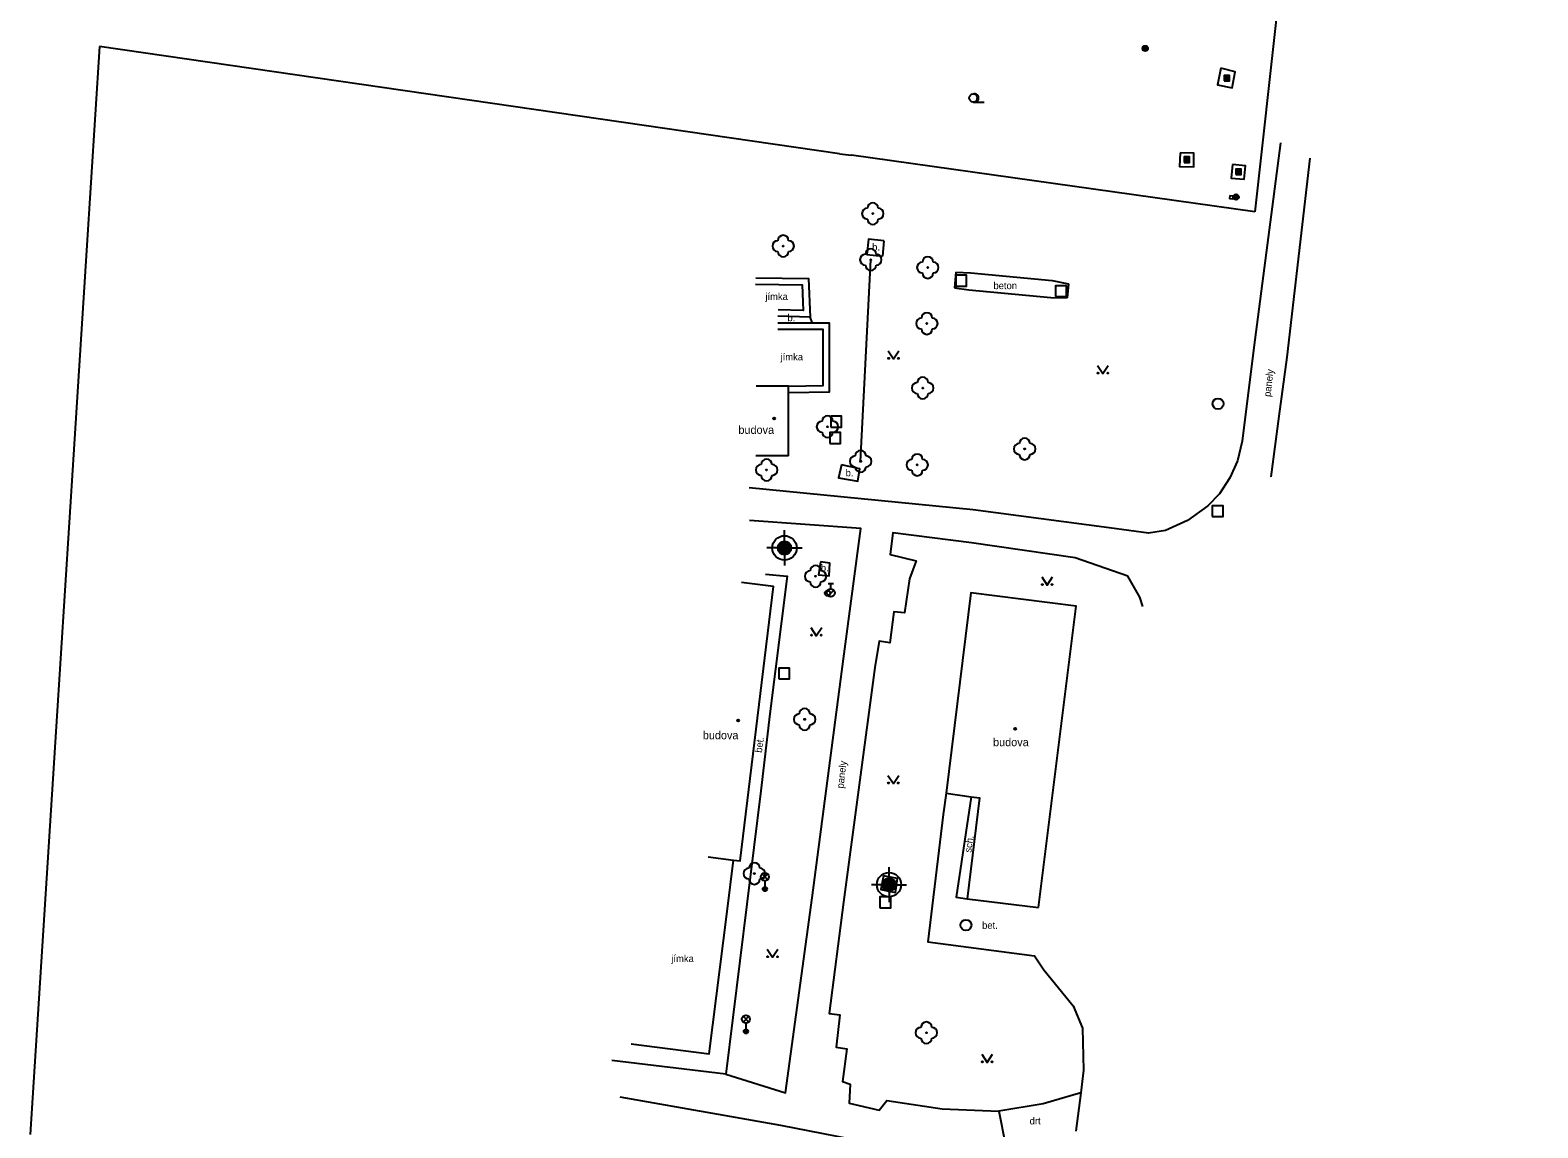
# Model space of a CAD drawing. Extents: x -540235 to -537963, y -1184915 to -1183660.
# Drawn here: x -540179 to -540039.8, y -1183965.3 to -1183863.9 of the extents above; entities that cross this region are included whole.
import ezdxf

# ---------------------------------------------------------------- set-up
doc = ezdxf.new("R2010")
doc.units = 0
for name, color, linetype in [('Vrstva 10', 7, 'Continuous'), ('Vrstva 11', 7, 'Continuous'), ('Vrstva 21', 7, 'Continuous'), ('Vrstva 22', 7, 'Continuous'), ('Vrstva 24', 7, 'Continuous'), ('Vrstva 25', 7, 'Continuous'), ('Vrstva 26', 7, 'Continuous'), ('Vrstva 27', 7, 'Continuous'), ('Vrstva 28', 7, 'Continuous'), ('Vrstva 33', 7, 'Continuous'), ('Vrstva 35', 7, 'Continuous'), ('Vrstva 36', 7, 'Continuous'), ('Vrstva 39', 7, 'Continuous'), ('Vrstva 40', 7, 'Continuous'), ('Vrstva 41', 7, 'Continuous'), ('Vrstva 5', 7, 'Continuous'), ('Vrstva 7', 7, 'Continuous'), ('Vrstva 8', 7, 'Continuous')]:
    doc.layers.add(name, color=color, linetype=linetype)

msp = doc.modelspace()

# ---------------------------------------------------------------- linework, layer by layer
at = {"layer": 'Vrstva 10'}
for points in [[(-540094.47, -1183934.39), (-540094.73, -1183936.35), (-540096.14, -1183948.09), (-540086.31, -1183949.41), (-540085.44, -1183950.68), (-540082.72, -1183954.01), (-540081.86, -1183956.08), (-540081.78, -1183959.97), (-540082.04, -1183962.04)], [(-540082.04, -1183962.04), (-540082.48, -1183965.59)]]:
    msp.add_lwpolyline(points, dxfattribs=at)
at = {"layer": 'Vrstva 11'}
msp.add_line((-540100.2, -1183883.36), (-540100.34, -1183884.79), dxfattribs=at)
for points in [[(-540063.59, -1183874.34), (-540066.05, -1183893.22), (-540067.13, -1183901.88), (-540067.57, -1183903.7), (-540068.27, -1183905.25), (-540069.24, -1183906.74), (-540070.3, -1183907.86), (-540072.17, -1183909.19), (-540074.22, -1183910.11), (-540075.78, -1183910.38), (-540079.41, -1183909.87), (-540091.96, -1183908.22), (-540112.64, -1183906.17)], [(-540060.89, -1183875.73), (-540063, -1183894.11), (-540063.75, -1183899.57), (-540064.48, -1183905.17)], [(-540100.2, -1183883.36), (-540101.6331, -1183883.2197), (-540101.7731, -1183884.6497), (-540100.34, -1183884.79)], [(-540106.79, -1183890.97), (-540107.02, -1183890.42)], [(-540104.13, -1183904.05), (-540104.4, -1183905.27), (-540102.6, -1183905.57), (-540102.41, -1183904.42), (-540104.13, -1183904.05)], [(-540114.79, -1183960.33), (-540109.3, -1183962.06), (-540106.84, -1183944.05), (-540103.94, -1183921.98), (-540102.32, -1183909.95), (-540112.6, -1183909.21)], [(-540076.31, -1183917.14), (-540076.57, -1183916.27), (-540077.68, -1183914.35), (-540082.56, -1183912.64), (-540092.13, -1183911.25), (-540099.38, -1183910.33), (-540099.63, -1183912.33), (-540097.24, -1183912.93), (-540097.85, -1183914.59), (-540098.3, -1183917.71), (-540099.28, -1183917.62), (-540099.67, -1183920.5), (-540100.63, -1183920.34), (-540101.04, -1183922.76), (-540103.92, -1183944.43), (-540105.27, -1183954.72), (-540104.28, -1183954.85), (-540104.6, -1183957.82), (-540103.64, -1183957.98), (-540104.02, -1183961.01), (-540103.31, -1183961.24), (-540103.4, -1183963), (-540100.63, -1183963.66), (-540099.93, -1183962.77), (-540094.82, -1183963.54), (-540089.6, -1183963.73)], [(-540106.07, -1183913.02), (-540106.23, -1183914.23), (-540105.25, -1183914.31), (-540105.19, -1183913.14), (-540106.07, -1183913.02)], [(-540092.16, -1183934.71), (-540093.53, -1183943.98), (-540092.51, -1183944.12)], [(-540100.23, -1183942), (-540100.49, -1183943.27), (-540099.12, -1183943.56), (-540098.94, -1183942.25), (-540100.23, -1183942)], [(-540082.04, -1183962.04), (-540085.49, -1183963.05), (-540089.6, -1183963.73)], [(-540089.02, -1183966.69), (-540095.17, -1183966.92), (-540097.23, -1183967.24), (-540097.81, -1183968.1), (-540087.88, -1183969.31), (-540088.51, -1183975.15), (-540101.65, -1183974.03), (-540100.59, -1183966.86), (-540109.71, -1183965.07), (-540124.55, -1183962.46)], [(-540089.6, -1183963.73), (-540089.02, -1183966.69)]]:
    msp.add_lwpolyline(points, dxfattribs=at)
at = {"layer": 'Vrstva 21'}
msp.add_lwpolyline([(-540102.35, -1183903.74), (-540101.41, -1183885.12)], dxfattribs=at)
at = {"layer": 'Vrstva 22'}
for centre in [(-540101.23, -1183880.86), (-540109.5, -1183883.86), (-540101.41, -1183885.12), (-540096.15, -1183885.84), (-540096.24, -1183891.01), (-540096.62, -1183896.97), (-540105.41, -1183900.54), (-540102.35, -1183903.74), (-540087.21, -1183902.59), (-540111.03, -1183904.53), (-540097.13, -1183904.06), (-540106.51, -1183914.35), (-540107.52, -1183927.56), (-540112.16, -1183941.8), (-540096.28, -1183956.5)]:
    msp.add_circle(centre, 0.05, dxfattribs=at)
for centre, start, end in [((-540101.23, -1183880.36), 0, 180), ((-540101.73, -1183880.86), 90, 270), ((-540101.23, -1183881.36), 180, 0), ((-540100.73, -1183880.86), 270, 90), ((-540109.5, -1183883.36), 0, 180), ((-540110, -1183883.86), 90, 270), ((-540109.5, -1183884.36), 180, 0), ((-540109, -1183883.86), 270, 90), ((-540101.41, -1183884.62), 0, 180), ((-540101.91, -1183885.12), 90, 270), ((-540101.41, -1183885.62), 180, 0), ((-540100.91, -1183885.12), 270, 90), ((-540096.65, -1183885.84), 90, 270), ((-540096.15, -1183885.34), 0, 180), ((-540095.65, -1183885.84), 270, 90), ((-540096.15, -1183886.34), 180, 0), ((-540096.74, -1183891.01), 90, 270), ((-540096.24, -1183890.51), 0, 180), ((-540095.74, -1183891.01), 270, 90), ((-540096.24, -1183891.51), 180, 0), ((-540097.12, -1183896.97), 90, 270), ((-540096.62, -1183896.47), 0, 180), ((-540096.12, -1183896.97), 270, 90), ((-540096.62, -1183897.47), 180, 0), ((-540105.41, -1183900.04), 0, 180), ((-540105.91, -1183900.54), 90, 270), ((-540105.41, -1183901.04), 180, 0), ((-540104.91, -1183900.54), 270, 90), ((-540087.71, -1183902.59), 90, 270), ((-540087.21, -1183902.09), 0, 180), ((-540086.71, -1183902.59), 270, 90), ((-540111.03, -1183904.03), 0, 180), ((-540102.85, -1183903.74), 90, 270), ((-540102.35, -1183903.24), 0, 180), ((-540101.85, -1183903.74), 270, 90), ((-540097.63, -1183904.06), 90, 270), ((-540097.13, -1183903.56), 0, 180), ((-540096.63, -1183904.06), 270, 90), ((-540087.21, -1183903.09), 180, 0), ((-540111.53, -1183904.53), 90, 270), ((-540111.03, -1183905.03), 180, 0), ((-540110.53, -1183904.53), 270, 90), ((-540102.35, -1183904.24), 180, 0), ((-540097.13, -1183904.56), 180, 0), ((-540106.51, -1183913.85), 0, 180), ((-540107.01, -1183914.35), 90, 270), ((-540106.51, -1183914.85), 180, 0), ((-540106.01, -1183914.35), 270, 90), ((-540108.02, -1183927.56), 90, 270), ((-540107.52, -1183927.06), 0, 180), ((-540107.02, -1183927.56), 270, 90), ((-540107.52, -1183928.06), 180, 0), ((-540112.66, -1183941.8), 90, 270), ((-540112.16, -1183941.3), 0, 180), ((-540111.66, -1183941.8), 270, 90), ((-540112.16, -1183942.3), 180, 0), ((-540096.78, -1183956.5), 90, 270), ((-540096.28, -1183956), 0, 180), ((-540095.78, -1183956.5), 270, 90), ((-540096.28, -1183957), 180, 0)]:
    msp.add_arc(centre, 0.5, start, end, dxfattribs=at)
at = {"layer": 'Vrstva 24'}
for points in [[(-540068.28, -1183879.2), (-540068.3, -1183879.5)], [(-540068.28, -1183879.2), (-540067.9807, -1183879.22), (-540068.0007, -1183879.52), (-540068.3, -1183879.5)]]:
    msp.add_lwpolyline(points, dxfattribs=at)
at = {"layer": 'Vrstva 25'}
for points in [[(-540068.81, -1183868.61), (-540068.31, -1183868.61), (-540068.31, -1183868.11), (-540068.81, -1183868.11)], [(-540068.76, -1183868.56), (-540068.36, -1183868.56), (-540068.36, -1183868.16), (-540068.76, -1183868.16)], [(-540068.71, -1183868.51), (-540068.41, -1183868.51), (-540068.41, -1183868.21), (-540068.71, -1183868.21)], [(-540068.66, -1183868.46), (-540068.46, -1183868.46), (-540068.46, -1183868.26), (-540068.66, -1183868.26)], [(-540068.61, -1183868.41), (-540068.51, -1183868.41), (-540068.51, -1183868.31), (-540068.61, -1183868.31)], [(-540072.4871, -1183876.1277), (-540071.9871, -1183876.1277), (-540071.9871, -1183875.6277), (-540072.4871, -1183875.6277)], [(-540072.4371, -1183876.0777), (-540072.0371, -1183876.0777), (-540072.0371, -1183875.6777), (-540072.4371, -1183875.6777)], [(-540072.3871, -1183876.0277), (-540072.0871, -1183876.0277), (-540072.0871, -1183875.7277), (-540072.3871, -1183875.7277)], [(-540072.3371, -1183875.9777), (-540072.1371, -1183875.9777), (-540072.1371, -1183875.7777), (-540072.3371, -1183875.7777)], [(-540072.2871, -1183875.9277), (-540072.1871, -1183875.9277), (-540072.1871, -1183875.8277), (-540072.2871, -1183875.8277)], [(-540067.73, -1183877.26), (-540067.23, -1183877.26), (-540067.23, -1183876.76), (-540067.73, -1183876.76)], [(-540067.68, -1183877.21), (-540067.28, -1183877.21), (-540067.28, -1183876.81), (-540067.68, -1183876.81)], [(-540067.63, -1183877.16), (-540067.33, -1183877.16), (-540067.33, -1183876.86), (-540067.63, -1183876.86)], [(-540067.58, -1183877.11), (-540067.38, -1183877.11), (-540067.38, -1183876.91), (-540067.58, -1183876.91)], [(-540067.53, -1183877.06), (-540067.43, -1183877.06), (-540067.43, -1183876.96), (-540067.53, -1183876.96)]]:
    msp.add_lwpolyline(points, close=True, dxfattribs=at)
for centre, radius in [((-540076.08, -1183865.61), 0.25), ((-540076.08, -1183865.61), 0.2), ((-540076.08, -1183865.61), 0.15), ((-540076.08, -1183865.61), 0.1), ((-540076.08, -1183865.61), 0.05), ((-540067.7, -1183879.33), 0.25), ((-540067.7, -1183879.33), 0.2), ((-540067.7, -1183879.33), 0.15), ((-540067.7, -1183879.33), 0.1), ((-540067.7, -1183879.33), 0.05)]:
    msp.add_circle(centre, radius, dxfattribs=at)
at = {"layer": 'Vrstva 26'}
for points in [[(-540093.57, -1183887.55), (-540092.57, -1183887.55), (-540092.57, -1183886.55), (-540093.57, -1183886.55)], [(-540084.35, -1183888.52), (-540083.35, -1183888.52), (-540083.35, -1183887.52), (-540084.35, -1183887.52)], [(-540105.11, -1183900.58), (-540104.11, -1183900.58), (-540104.11, -1183899.58), (-540105.11, -1183899.58)], [(-540105.2, -1183902.08), (-540104.2, -1183902.08), (-540104.2, -1183901.08), (-540105.2, -1183901.08)], [(-540069.9, -1183908.84), (-540068.9, -1183908.84), (-540068.9, -1183907.84), (-540069.9, -1183907.84)], [(-540109.91, -1183923.82), (-540108.91, -1183923.82), (-540108.91, -1183922.82), (-540109.91, -1183922.82)], [(-540100.57, -1183944.96), (-540099.57, -1183944.96), (-540099.57, -1183943.96), (-540100.57, -1183943.96)]]:
    msp.add_lwpolyline(points, close=True, dxfattribs=at)
at = {"layer": 'Vrstva 27'}
for centre in [(-540069.36, -1183898.42), (-540092.63, -1183946.56)]:
    msp.add_circle(centre, 0.5, dxfattribs=at)
at = {"layer": 'Vrstva 28'}
for p, q in [((-540105.36, -1183915.005), (-540104.86, -1183915.005)), ((-540105.11, -1183915.505), (-540105.11, -1183915.005)), ((-540105.368, -1183916.152), (-540104.838, -1183915.622))]:
    msp.add_line(p, q, dxfattribs=at)
for centre, radius in [((-540105.4, -1183915.91), 0.25), ((-540105.11, -1183915.88), 0.375)]:
    msp.add_circle(centre, radius, dxfattribs=at)
at = {"layer": 'Vrstva 33'}
for p, q in [((-540111.455, -1183942.37), (-540110.925, -1183941.84)), ((-540111.455, -1183941.84), (-540110.925, -1183942.37)), ((-540111.19, -1183942.48), (-540111.19, -1183943.23)), ((-540113.205, -1183955.51), (-540112.675, -1183954.98)), ((-540113.205, -1183954.98), (-540112.675, -1183955.51)), ((-540112.94, -1183955.62), (-540112.94, -1183956.37))]:
    msp.add_line(p, q, dxfattribs=at)
for centre, radius in [((-540111.19, -1183942.105), 0.375), ((-540111.19, -1183943.23), 0.2), ((-540111.19, -1183943.23), 0.1445), ((-540111.19, -1183943.23), 0.0876), ((-540112.94, -1183955.245), 0.375), ((-540112.94, -1183956.37), 0.2), ((-540112.94, -1183956.37), 0.1445), ((-540112.94, -1183956.37), 0.0876)]:
    msp.add_circle(centre, radius, dxfattribs=at)
at = {"layer": 'Vrstva 35'}
for p, q in [((-540109.38, -1183911.105), (-540109.38, -1183910.105)), ((-540110.005, -1183911.73), (-540111.005, -1183911.73)), ((-540110.003, -1183911.691), (-540109.102, -1183911.171)), ((-540109.993, -1183911.847), (-540108.972, -1183911.257)), ((-540109.962, -1183911.506), (-540109.283, -1183911.113)), ((-540109.951, -1183911.984), (-540108.874, -1183911.362)), ((-540109.88, -1183912.105), (-540108.806, -1183911.484)), ((-540109.78, -1183912.209), (-540108.765, -1183911.623)), ((-540109.648, -1183912.294), (-540108.758, -1183911.78)), ((-540109.463, -1183912.349), (-540108.803, -1183911.968)), ((-540108.755, -1183911.73), (-540107.755, -1183911.73)), ((-540109.38, -1183912.355), (-540109.38, -1183913.355)), ((-540099.73, -1183942.205), (-540099.73, -1183941.205)), ((-540100.355, -1183942.83), (-540101.355, -1183942.83)), ((-540100.353, -1183942.791), (-540099.452, -1183942.271)), ((-540100.343, -1183942.947), (-540099.322, -1183942.357)), ((-540100.312, -1183942.606), (-540099.633, -1183942.213)), ((-540100.301, -1183943.084), (-540099.224, -1183942.462)), ((-540100.23, -1183943.205), (-540099.156, -1183942.584)), ((-540100.13, -1183943.309), (-540099.115, -1183942.723)), ((-540099.105, -1183942.83), (-540098.105, -1183942.83)), ((-540099.998, -1183943.394), (-540099.108, -1183942.88)), ((-540099.813, -1183943.449), (-540099.153, -1183943.068)), ((-540099.73, -1183943.455), (-540099.73, -1183944.455))]:
    msp.add_line(p, q, dxfattribs=at)
for centre, radius in [((-540109.38, -1183911.73), 1.125), ((-540109.38, -1183911.73), 0.625), ((-540099.73, -1183942.83), 1.125), ((-540099.73, -1183942.83), 0.625)]:
    msp.add_circle(centre, radius, dxfattribs=at)
at = {"layer": 'Vrstva 36'}
msp.add_line((-540091.959, -1183870.5565), (-540090.959, -1183870.5565), dxfattribs=at)
for points in [[(-540099.812, -1183893.5226), (-540099.312, -1183894.2726), (-540098.812, -1183893.5226)], [(-540080.4922, -1183894.8888), (-540079.9922, -1183895.6388), (-540079.4922, -1183894.8888)], [(-540085.6335, -1183914.4138), (-540085.1335, -1183915.1638), (-540084.6335, -1183914.4138)], [(-540106.9456, -1183919.088), (-540106.4456, -1183919.838), (-540105.9456, -1183919.088)], [(-540099.831, -1183932.7388), (-540099.331, -1183933.4888), (-540098.831, -1183932.7388)], [(-540110.9837, -1183948.7846), (-540110.4837, -1183949.5346), (-540109.9837, -1183948.7846)], [(-540091.1713, -1183958.4821), (-540090.6713, -1183959.2321), (-540090.1713, -1183958.4821)]]:
    msp.add_lwpolyline(points, dxfattribs=at)
for centre, radius in [((-540091.959, -1183870.1811), 0.375), ((-540099.7622, -1183894.2224), 0.05), ((-540098.8628, -1183894.2224), 0.05), ((-540080.4424, -1183895.5886), 0.05), ((-540079.543, -1183895.5886), 0.05), ((-540085.5837, -1183915.1136), 0.05), ((-540084.6843, -1183915.1136), 0.05), ((-540106.8958, -1183919.7878), 0.05), ((-540105.9964, -1183919.7878), 0.05), ((-540099.7812, -1183933.4386), 0.05), ((-540098.8818, -1183933.4386), 0.05), ((-540110.9339, -1183949.4844), 0.05), ((-540110.0345, -1183949.4844), 0.05), ((-540091.1215, -1183959.1819), 0.05), ((-540090.2221, -1183959.1819), 0.05)]:
    msp.add_circle(centre, radius, dxfattribs=at)
msp.add_arc((-540091.834, -1183870.1811), 0.375, 260.405931, 99.594069, dxfattribs=at)
at = {"layer": 'Vrstva 39'}
for centre, radius in [((-540110.3423, -1183899.7798), 0.09), ((-540110.3423, -1183899.7798), 0.0398), ((-540113.6683, -1183927.6777), 0.09), ((-540113.6683, -1183927.6777), 0.0398), ((-540088.0919, -1183928.4405), 0.09), ((-540088.0919, -1183928.4405), 0.0398)]:
    msp.add_circle(centre, radius, dxfattribs=at)
at = {"layer": 'Vrstva 5'}
for points in [[(-540109.01, -1183896.78), (-540111.9907, -1183896.78)], [(-540109.0109, -1183897.3809), (-540109.01, -1183896.78)], [(-540109.02, -1183903.23), (-540109.0109, -1183897.3809)], [(-540109.02, -1183903.23), (-540112.02, -1183903.2253)], [(-540116.4381, -1183940.2679), (-540114.0857, -1183940.5539), (-540113.46, -1183940.63), (-540110.38, -1183915.3), (-540113.3581, -1183914.9379)], [(-540085.92, -1183944.92), (-540082.45, -1183917.1), (-540092.19, -1183915.89), (-540094.47, -1183934.39)], [(-540094.47, -1183934.39), (-540092.16, -1183934.71)], [(-540092.16, -1183934.71), (-540091.37, -1183934.8), (-540092.51, -1183944.12), (-540085.92, -1183944.92)]]:
    msp.add_lwpolyline(points, dxfattribs=at)
at = {"layer": 'Vrstva 7'}
for p, q in [((-540172.61, -1183865.42), (-540179.01, -1183965.9)), ((-540104.3, -1183875.33), (-540172.61, -1183865.42)), ((-540065.95, -1183880.71), (-540103.18, -1183875.45)), ((-540093.553, -1183886.2601), (-540093.7, -1183887.73)), ((-540083.16, -1183887.35), (-540083.29, -1183888.65))]:
    msp.add_line(p, q, dxfattribs=at)
for points in [[(-540039.84, -1183660.26), (-540042.79, -1183684.34), (-540052.88, -1183768.18), (-540059.63, -1183823.51), (-540065.95, -1183880.71)], [(-540069.1, -1183867.43), (-540069.4, -1183868.96), (-540068.06, -1183869.25), (-540067.77, -1183867.78), (-540069.1, -1183867.43)], [(-540072.85, -1183875.24), (-540072.91, -1183876.5), (-540071.61, -1183876.53), (-540071.58, -1183875.27), (-540072.85, -1183875.24)], [(-540068.02, -1183876.34), (-540068.14, -1183877.58), (-540066.94, -1183877.68), (-540066.82, -1183876.44), (-540068.02, -1183876.34)], [(-540112.04, -1183886.78), (-540107.16, -1183886.85), (-540107.02, -1183890.42)], [(-540093.553, -1183886.2601), (-540092.17, -1183886.34), (-540084.66, -1183887.04), (-540083.16, -1183887.35)], [(-540112.0486, -1183887.3799), (-540107.7373, -1183887.4418), (-540107.6447, -1183889.803), (-540109.9738, -1183889.7402)], [(-540093.7, -1183887.73), (-540092.37, -1183887.89), (-540084.805, -1183888.5951), (-540083.29, -1183888.65)], [(-540107.02, -1183890.42), (-540109.99, -1183890.34)], [(-540106.79, -1183890.97), (-540109.99, -1183890.97)], [(-540109.0109, -1183897.3809), (-540105.22, -1183897.32), (-540105.21, -1183890.97), (-540106.79, -1183890.97)], [(-540109.0206, -1183896.7802), (-540105.8199, -1183896.7288), (-540105.8118, -1183891.5708), (-540109.99, -1183891.5708)], [(-540109.0206, -1183896.7802), (-540105.8199, -1183896.7288), (-540105.8118, -1183891.5708), (-540109.99, -1183891.5708)], [(-540111.12, -1183914.16), (-540109.14, -1183914.35), (-540110.72, -1183927.06), (-540111.57, -1183934.15), (-540114.79, -1183960.33), (-540125.32, -1183959.05)], [(-540123.52, -1183957.53), (-540116.33, -1183958.44), (-540114.68, -1183945.29), (-540114.0857, -1183940.5539)]]:
    msp.add_lwpolyline(points, dxfattribs=at)
at = {"layer": 'Vrstva 8'}
msp.add_line((-540104.3, -1183875.33), (-540103.18, -1183875.45), dxfattribs=at)

# ---------------------------------------------------------------- texts
at = {"layer": 'Vrstva 40'}
for s, p in [('b.', (-540101.284, -1183884.274)), ('beton', (-540090.091, -1183887.837)), ('jímka', (-540111.144, -1183888.84)), ('b.', (-540109.106, -1183890.793)), ('jímka', (-540109.742, -1183894.414)), ('b.', (-540103.739, -1183905.12)), ('b.', (-540106.024, -1183913.897)), ('bet.', (-540091.137, -1183946.906)), ('jímka', (-540119.825, -1183949.968)), ('drt', (-540086.751, -1183964.965))]:
    msp.add_text(s, height=0.65, dxfattribs=at).set_placement(p)
for s, rotation, p in [('panely', 83.78345, (-540064.512, -1183897.81)), ('bet.', 82.453369, (-540111.471, -1183930.674)), ('panely', 83.78345, (-540103.929, -1183933.967)), ('sch.', 81.375258, (-540092.145, -1183939.897))]:
    msp.add_text(s, height=0.65, rotation=rotation, dxfattribs=at).set_placement(p)
at = {"layer": 'Vrstva 41'}
for p in [(-540113.631, -1183901.198), (-540116.919, -1183929.399), (-540090.125, -1183930.041)]:
    msp.add_text('budova', height=0.75, dxfattribs=at).set_placement(p)

doc.saveas('drawing.dxf')
